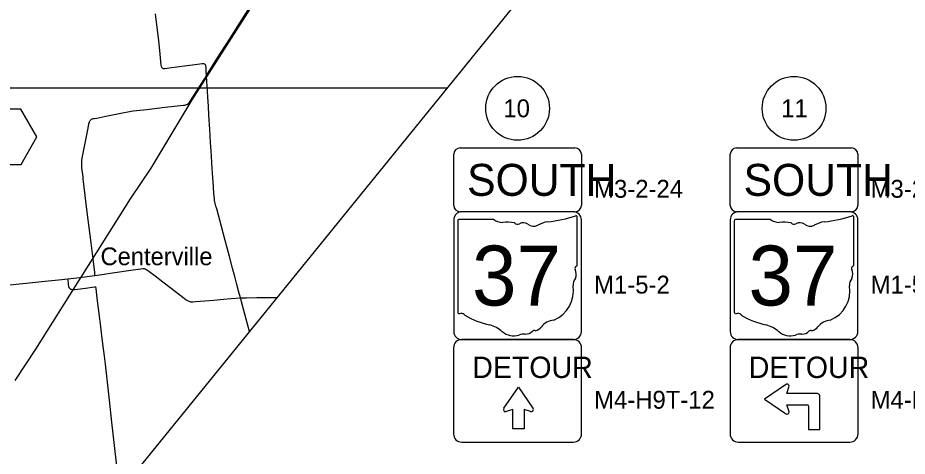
# Model space of a CAD drawing. Extents: x 0 to 680, y 0 to 440.
# Drawn here: x 332.1 to 471.5, y 150.5 to 219.2 of the extents above; entities that cross this region are included whole.
import ezdxf

# ---------------------------------------------------------------- set-up
doc = ezdxf.new("R2010")
doc.units = 0
for name, color, linetype in [('DV_X_County_Line', 7, 'Continuous'), ('GM_X_County_Road', 7, 'Continuous'), ('GM_X_State_Route', 7, 'Continuous'), ('GM_X_Township_Road', 7, 'Continuous'), ('GM_X_Unincorporated_Text', 7, 'Continuous'), ('RD_X_RR_2', 7, 'Continuous'), ('SH_Text', 7, 'Continuous'), ('SN_P_Signs', 7, 'Continuous'), ('SN_P_Text', 7, 'Continuous')]:
    doc.layers.add(name, color=color, linetype=linetype)

msp = doc.modelspace()

# ---------------------------------------------------------------- linework, layer by layer
at = {"layer": 'DV_X_County_Line'}
msp.add_line((399.36, 208.16), (30, 208.16), dxfattribs=at)
at = {"layer": 'GM_X_County_Road'}
for points in [[(246.72, 179.99), (247.37, 174.65), (247.71, 172.04), (248.09, 168.68), (248.13, 168.39), (248.18, 168.25), (248.32, 168.12), (248.56, 168.06), (248.87, 168.06), (270.78, 170.66), (313.8, 175.57), (322.56, 176.52), (329.32, 177.23), (332.35, 177.54), (334.92, 177.78)], [(344.13, 178.84), (345.61, 179.06), (346.91, 179.25), (350.16, 179.72), (351.35, 179.89), (351.66, 179.91), (351.77, 179.91), (351.88, 179.91), (351.97, 179.88), (352.06, 179.85), (352.28, 179.73), (352.64, 179.49), (353.59, 178.75), (354.81, 177.82), (356.11, 176.82), (357.93, 175.43), (358.47, 175.04), (358.76, 174.87), (358.88, 174.82), (359.03, 174.76), (359.16, 174.73), (359.36, 174.72), (359.51, 174.72), (359.95, 174.74), (361.37, 174.87), (362.79, 174.99), (364.31, 175.12), (365.51, 175.23), (366.93, 175.32), (366.99, 175.33)], [(339.93, 178.32), (341.82, 178.54), (344.1, 178.83), (344.13, 178.84)], [(334.92, 177.78), (335.83, 177.88), (338.99, 178.22), (339.93, 178.32)], [(366.99, 175.33), (367.91, 175.35), (369.55, 175.36), (370.98, 175.38), (372.51, 175.39), (372.72, 175.4)], [(368.4, 170.08), (367.16, 174.71), (367.02, 175.21), (366.99, 175.33)]]:
    msp.add_lwpolyline(points, dxfattribs=at)
at = {"layer": 'GM_X_State_Route'}
msp.add_lwpolyline([(332.56, 204.87), (327.56, 204.85), (325.07, 200.51), (327.59, 196.19), (332.59, 196.21), (335.07, 200.54)], close=True, dxfattribs=at)
at = {"layer": 'GM_X_Township_Road'}
for points in [[(361.66, 210.13), (363.29, 212.73), (365.29, 215.87), (367.45, 219.28), (370.13, 223.47)], [(361.66, 210.13), (361.65, 210.21), (361.62, 210.66), (361.59, 211.16), (361.58, 211.49), (361.57, 211.6), (361.54, 211.7), (361.5, 211.79), (361.44, 211.87), (361.36, 211.93), (361.27, 211.97), (361.17, 211.99), (361.09, 211.99), (360.96, 211.99), (359.44, 211.76), (356.19, 211.32), (355.11, 211.18), (354.99, 211.18), (354.88, 211.2), (354.81, 211.22), (354.77, 211.25), (354.69, 211.32), (354.63, 211.42), (354.59, 211.53), (354.55, 211.75), (354.34, 214.04), (354.17, 215.56), (353.64, 219.79)], [(342.33, 193.96), (342.3, 194.27), (342.13, 195.69), (342.1, 196.11), (342.09, 196.33), (342.09, 196.66), (342.11, 196.84), (342.16, 197.2), (342.21, 197.48), (342.84, 200.61), (343.09, 201.91), (343.2, 202.56), (343.25, 202.73), (343.3, 202.87), (343.34, 202.97), (343.42, 203.1), (343.47, 203.16), (343.55, 203.23), (343.65, 203.29), (343.78, 203.35), (343.91, 203.39), (344.02, 203.41), (344.45, 203.48), (345.85, 203.77), (348.74, 204.36), (349.31, 204.46), (349.82, 204.54), (350.14, 204.59), (350.67, 204.65), (352.31, 204.84), (355.14, 205.16), (358.07, 205.48), (358.25, 205.51), (358.4, 205.54), (358.51, 205.58), (358.62, 205.62), (358.71, 205.67), (358.8, 205.74), (358.89, 205.81), (358.96, 205.89), (359.17, 206.15), (359.69, 206.99), (361.37, 209.67), (361.66, 210.13)], [(362.5, 196.44), (362.49, 196.53), (362.38, 198.38), (362.31, 199.59), (362.24, 200.74), (362.19, 201.68), (362.04, 203.96), (361.96, 205.27), (361.86, 206.8), (361.76, 208.48), (361.72, 209.19), (361.69, 209.59), (361.68, 209.75), (361.66, 210.13)], [(366.99, 175.33), (366.75, 176.24), (366.43, 177.44), (366.15, 178.48), (365.74, 180), (365.25, 181.81), (364.94, 182.96), (364.58, 184.3), (364.32, 185.3), (363.99, 186.52), (363.26, 189.27), (363.14, 189.68), (363.09, 189.89), (363.03, 190.14), (362.98, 190.37), (362.93, 190.61), (362.91, 190.77), (362.85, 191.26), (362.81, 191.73), (362.7, 193.56), (362.67, 194.14), (362.5, 196.44)], [(344.13, 178.84), (344.15, 178.96), (344.15, 179.08), (344.14, 179.3), (343.93, 181.03), (343.57, 183.96), (342.97, 188.74), (342.33, 193.96)], [(340.21, 176.78), (340.16, 176.84), (340.13, 176.89), (340.11, 176.95), (340.09, 177), (340.08, 177.06), (339.96, 178.08), (339.93, 178.32)], [(340.21, 176.78), (340.28, 176.72), (340.32, 176.7), (340.37, 176.68), (340.42, 176.67), (340.51, 176.65), (340.64, 176.64), (340.79, 176.64), (340.96, 176.64), (341.5, 176.7), (342.68, 176.87), (344.09, 177.04), (344.32, 177.07)], [(347.73, 148), (347.72, 148.1), (346.84, 155.85), (346.45, 159.32), (346.12, 162.15), (345.8, 164.96), (345.61, 166.59), (345.48, 167.69), (345.2, 169.86), (345.08, 170.81), (344.93, 172.03), (344.54, 175.26), (344.36, 176.79), (344.32, 177.07)]]:
    msp.add_lwpolyline(points, dxfattribs=at)
at = {"layer": 'RD_X_RR_2'}
msp.add_lwpolyline([(331.67, 162.41), (334.88, 167.32), (349.73, 190.85), (352.96, 195.61), (359.41, 206.32), (365.59, 215.99), (372.38, 226.62)], dxfattribs=at)
at = {"layer": 'SH_Text'}
msp.add_lwpolyline([(30, 430), (466.92, 430), (466.92, 291.27), (342.9, 138.72), (30, 138.72)], close=True, dxfattribs=at)
at = {"layer": 'SN_P_Signs'}
for p, q in [((401.43, 198.8), (419.43, 198.8)), ((444.78, 198.8), (462.78, 198.8)), ((400.43, 189.8), (400.43, 197.8)), ((420.43, 197.8), (420.43, 189.8)), ((443.78, 189.8), (443.78, 197.8)), ((463.78, 197.8), (463.78, 189.8)), ((419.43, 188.8), (401.43, 188.8)), ((462.78, 188.8), (444.78, 188.8)), ((401.04, 187.36), (401.04, 173.13)), ((406.72, 187.6), (401.23, 187.6)), ((419.79, 180.51), (419.79, 187.96)), ((444.4, 187.36), (444.4, 173.13)), ((450.07, 187.6), (444.58, 187.6)), ((463.14, 180.51), (463.14, 187.96)), ((419.79, 180.51), (419.79, 180.51)), ((463.14, 180.51), (463.14, 180.51)), ((408.28, 158.04), (410.56, 161.36)), ((410.56, 161.36), (412.8, 158.08)), ((452.42, 161.72), (449.15, 159.48)), ((452.66, 160.36), (452.99, 161.49)), ((449.15, 159.48), (452.42, 157.24)), ((457.43, 160.36), (452.66, 160.36)), ((457.43, 160.36), (457.43, 160.36)), ((457.8, 154.71), (457.8, 159.98)), ((409.68, 157.85), (408.65, 157.53)), ((409.68, 154.84), (409.68, 157.85)), ((412.47, 157.53), (411.44, 157.85)), ((411.44, 157.85), (411.44, 154.84)), ((452.99, 157.47), (452.66, 158.6)), ((452.66, 158.6), (455.79, 158.6)), ((456.04, 158.35), (456.04, 154.71)), ((411.44, 154.84), (409.68, 154.84)), ((456.04, 154.71), (457.8, 154.71))]:
    msp.add_line(p, q, dxfattribs=at)
for points in [[(419.18, 188.8), (401.68, 188.8)], [(462.53, 188.8), (445.03, 188.8)], [(400.43, 187.55), (400.43, 170.05)], [(420.43, 170.05), (420.43, 187.55)], [(443.78, 187.55), (443.78, 170.05)], [(463.78, 170.05), (463.78, 187.55)], [(401.68, 168.8), (419.18, 168.8)], [(419.18, 168.8), (401.68, 168.8)], [(445.03, 168.8), (462.53, 168.8)], [(462.53, 168.8), (445.03, 168.8)], [(400.4, 167.52), (400.4, 154.03)], [(420.47, 154.03), (420.47, 167.52)], [(443.75, 167.52), (443.75, 154.03)], [(463.82, 154.03), (463.82, 167.52)], [(401.68, 152.74), (419.18, 152.74)], [(445.03, 152.74), (462.53, 152.74)]]:
    msp.add_lwpolyline(points, dxfattribs=at)
for centre in [(410.43, 205), (453.78, 205)]:
    msp.add_circle(centre, 5, dxfattribs=at)
for centre, radius, start, end in [((401.43, 197.8), 1, 90, 180), ((419.43, 197.8), 1, 0, 90), ((444.78, 197.8), 1, 90, 180), ((462.78, 197.8), 1, 0, 90), ((401.43, 189.8), 1, 180, 270), ((419.43, 189.8), 1, 270, 0), ((444.78, 189.8), 1, 180, 270), ((462.78, 189.8), 1, 270, 0), ((401.68, 187.55), 1.25, 90, 180), ((419.18, 187.55), 1.25, 0, 90), ((445.03, 187.55), 1.25, 90, 180), ((462.53, 187.55), 1.25, 0, 90), ((401.26, 187.39), 0.217, 98.1301, 188.1301), ((408.03, 189.26), 2.11, 231.6195, 271.1119), ((408.72, 179.61), 7.56, 80.4867, 94.9883), ((410.44, 187.46), 0.608, 219.7921, 297.1024), ((411.33, 185.82), 1.26, 54.4667, 119.1411), ((415.65, 183.26), 4, 97.3462, 120.7689), ((413.11, 207), 19.88, 275.8445, 288.9065), ((419.58, 187.99), 0.209, 351.8621, 97.738), ((444.61, 187.39), 0.217, 98.1301, 188.1301), ((451.38, 189.26), 2.11, 231.6195, 271.1119), ((452.08, 179.61), 7.56, 80.4867, 94.9883), ((453.79, 187.46), 0.608, 219.7921, 297.1024), ((454.69, 185.82), 1.26, 54.4667, 119.1411), ((459, 183.26), 4, 97.3462, 120.7689), ((456.47, 207), 19.88, 275.8445, 288.9065), ((462.94, 187.99), 0.209, 351.8621, 97.738), ((412.96, 188.07), 1.52, 233.8562, 294.8282), ((456.32, 188.07), 1.52, 233.8562, 294.8282), ((419.74, 179.97), 0.323, 107.944, 210.337), ((419.57, 180.48), 0.223, 289.6038, 7.7341), ((463.1, 179.97), 0.323, 107.944, 210.337), ((462.92, 180.48), 0.223, 289.6038, 7.7341), ((417.69, 179.02), 1.94, 340.033, 23.6496), ((461.04, 179.02), 1.94, 340.033, 23.6496), ((414.23, 176.45), 4.97, 292.3089, 8.9858), ((420.54, 177.4), 1.41, 136.8065, 186.9296), ((457.58, 176.45), 4.97, 292.3089, 8.9858), ((463.89, 177.4), 1.41, 136.8065, 186.9296), ((401.26, 173.1), 0.219, 171.9584, 258.3066), ((444.61, 173.1), 0.219, 171.9584, 258.3066), ((401.29, 174.55), 1.67, 267.339, 280.6039), ((401.63, 172.31), 0.603, 29.7484, 93.2717), ((409.25, 185.09), 14.36, 240.4129, 257.1985), ((416.32, 169.13), 2.72, 94.4031, 142.5768), ((444.65, 174.55), 1.67, 267.339, 280.6039), ((444.99, 172.31), 0.603, 29.7484, 93.2717), ((452.6, 185.09), 14.36, 240.4129, 257.1985), ((459.68, 169.13), 2.72, 94.4031, 142.5768), ((404.97, 166.73), 4.49, 47.1842, 75.836), ((413.06, 169.79), 0.428, 65.7517, 132.6484), ((412.87, 171.75), 1.61, 282.8732, 323.2771), ((448.32, 166.73), 4.49, 47.1842, 75.836), ((456.41, 169.79), 0.428, 65.7517, 132.6484), ((456.23, 171.75), 1.61, 282.8732, 323.2771), ((401.68, 167.52), 1.28, 90, 180), ((401.68, 170.05), 1.25, 180, 270), ((409.83, 172.24), 2.85, 230.7004, 286.2918), ((411.47, 167.32), 2.34, 85.6951, 111.2099), ((411.68, 171.17), 1.52, 268.777, 315.5493), ((419.18, 170.05), 1.25, 270, 0), ((419.18, 167.52), 1.28, 0, 90), ((445.03, 167.52), 1.28, 90, 180), ((445.03, 170.05), 1.25, 180, 270), ((453.18, 172.24), 2.85, 230.7004, 286.2918), ((454.83, 167.32), 2.34, 85.6951, 111.2099), ((455.03, 171.17), 1.52, 268.777, 315.5493), ((462.53, 170.05), 1.25, 270, 0), ((462.53, 167.52), 1.28, 0, 90), ((452.66, 161.49), 0.335, 0.0017, 134.9999), ((457.42, 159.98), 0.376, 0, 90), ((408.55, 157.85), 0.335, 145.4112, 287.2046), ((412.57, 157.85), 0.335, 252.7954, 45.0096), ((455.79, 158.35), 0.25, 0, 90), ((452.66, 157.47), 0.335, 225.0001, 0.0017), ((401.68, 154.03), 1.28, 180, 270), ((419.18, 154.03), 1.28, 270, 0), ((445.03, 154.03), 1.28, 180, 270), ((462.53, 154.03), 1.28, 270, 0)]:
    msp.add_arc(centre, radius, start, end, dxfattribs=at)

# ---------------------------------------------------------------- texts
at = {"layer": 'GM_X_Unincorporated_Text'}
msp.add_text('Centerville', height=2.78, rotation=0, dxfattribs=at).set_placement((345.04, 180.44))
at = {"layer": 'SN_P_Signs'}
for s, height, p in [('10', 2.8, (408.2, 203.6)), ('11', 2.8, (451.75, 203.6)), ('SOUTH', 5, (402.52, 191.3)), ('SOUTH', 5, (445.87, 191.3)), ('37', 9.375, (403.29, 174.13)), ('37', 9.375, (446.64, 174.13)), ('DETOUR', 3.345, (403.33, 162.78)), ('DETOUR', 3.345, (446.68, 162.78))]:
    msp.add_text(s, height=height, dxfattribs=at).set_placement(p)
at = {"layer": 'SN_P_Text'}
for s, p in [('M3-2-24', (422.43, 191)), ('M3-2-24', (465.78, 191)), ('M1-5-2', (422.43, 176)), ('M1-5-2', (465.78, 176)), ('M4-H9T-12', (422.43, 157.97)), ('M4-H9BL-12', (465.78, 157.97))]:
    msp.add_text(s, height=2.8, dxfattribs=at).set_placement(p)

doc.saveas('drawing.dxf')
